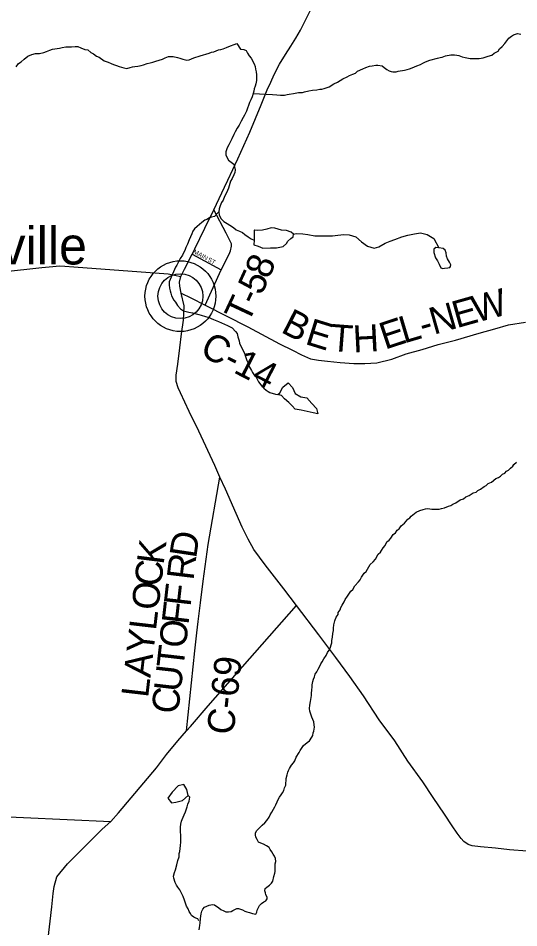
# Model space of a CAD drawing. Extents: x 1310247 to 1664935, y 235267 to 584339.
# Drawn here: x 1491906 to 1497464, y 346148 to 356246 of the extents above; entities that cross this region are included whole.
import ezdxf

# ---------------------------------------------------------------- set-up
doc = ezdxf.new("R2010")
doc.units = 0
for name, color, linetype in [('GM_X_County_Road', 7, 'Continuous'), ('GM_X_County_Road_Text', 7, 'Continuous'), ('GM_X_Minor_Lake', 7, 'Continuous'), ('GM_X_Minor_River', 7, 'Continuous'), ('GM_X_State_Route', 7, 'Continuous'), ('GM_X_Township_Road', 7, 'Continuous'), ('GM_X_Township_Road_Text', 7, 'Continuous'), ('GM_X_Township_Subdivision', 7, 'Continuous'), ('GM_X_Township_Subdivision_Text', 7, 'Continuous'), ('GM_X_Unincorporated', 7, 'Continuous'), ('GM_X_Unincorporated_Location', 7, 'Continuous'), ('GM_X_Unincorporated_Text', 7, 'Continuous')]:
    doc.layers.add(name, color=color, linetype=linetype)

msp = doc.modelspace()

# ---------------------------------------------------------------- linework, layer by layer
at = {"layer": 'GM_X_County_Road'}
for points in [[(1491734, 353430), (1492170, 353477), (1492252, 353485), (1492368, 353496), (1492426, 353492), (1492524, 353486), (1493570, 353407), (1493712, 353378)], [(1493716, 353192), (1493822, 353140)], [(1493822, 353140), (1493982, 353061), (1494456, 352818), (1494809, 352631), (1494952, 352559), (1495051, 352508), (1495150, 352466), (1495242, 352449), (1495341, 352439), (1495479, 352425), (1495633, 352411), (1495754, 352411), (1495887, 352419), (1496054, 352462), (1496214, 352518), (1496390, 352568), (1496570, 352622), (1496760, 352673), (1497025, 352750), (1497197, 352799), (1497351, 352841), (1497540, 352873)], [(1493776, 348333), (1493868, 349221), (1493889, 349421), (1493905, 349549), (1493930, 349754), (1493961, 349998), (1494016, 350403), (1494145, 351149)], [(1492058, 344014), (1492056, 344220), (1492071, 344510), (1492091, 344721), (1492130, 345110), (1492281, 346381), (1492294, 346529), (1492304, 346605), (1492334, 346713), (1492452, 346859), (1492839, 347242), (1492933, 347327), (1493021, 347424), (1493440, 347924), (1493552, 348071), (1493678, 348222), (1493776, 348333), (1493819, 348382), (1494015, 348612), (1494995, 349727)]]:
    msp.add_lwpolyline(points, dxfattribs=at)
at = {"layer": 'GM_X_Minor_Lake'}
for points in [[(1493794, 347618), (1493777, 347683), (1493746, 347739), (1493682, 347724), (1493614, 347655), (1493569, 347586)], [(1493569, 347586), (1493608, 347537), (1493655, 347544), (1493731, 347563), (1493794, 347618)], [(1493811, 347597), (1493794, 347618)]]:
    msp.add_lwpolyline(points, dxfattribs=at)
at = {"layer": 'GM_X_Minor_River'}
msp.add_line((1496575, 353695), (1496544, 353700), dxfattribs=at)
for points in [[(1494516, 355411), (1494731, 355397), (1494779, 355395), (1494820, 355390), (1494864, 355393), (1494892, 355397), (1494914, 355402), (1494961, 355410), (1495019, 355419), (1495063, 355422), (1495084, 355427), (1495134, 355441), (1495174, 355446), (1495221, 355451), (1495255, 355457), (1495279, 355458), (1495305, 355466), (1495358, 355485), (1495411, 355518), (1495451, 355536), (1495512, 355573), (1495559, 355596), (1495583, 355608), (1495620, 355623), (1495650, 355637), (1495675, 355658), (1495731, 355682), (1495766, 355697), (1495806, 355712), (1495836, 355718), (1495877, 355725), (1495899, 355725), (1495947, 355716), (1495969, 355700), (1495999, 355677), (1496026, 355660), (1496046, 355654), (1496066, 355650), (1496103, 355651), (1496125, 355657), (1496195, 355668), (1496224, 355677), (1496250, 355685), (1496280, 355694), (1496331, 355717), (1496371, 355731), (1496400, 355746), (1496428, 355760), (1496475, 355779), (1496560, 355802), (1496592, 355809), (1496612, 355813), (1496650, 355828), (1496709, 355840), (1496749, 355839), (1496775, 355836), (1496799, 355830), (1496837, 355817), (1496869, 355811), (1496923, 355800), (1496969, 355797), (1497024, 355798), (1497068, 355807), (1497125, 355824), (1497165, 355836), (1497190, 355857), (1497234, 355881), (1497251, 355905), (1497281, 355930), (1497308, 355964), (1497331, 355996), (1497355, 356023), (1497384, 356047), (1497404, 356061), (1497449, 356074), (1497487, 356069)], [(1491883, 355707), (1491911, 355741), (1491938, 355762), (1491972, 355790), (1492015, 355823), (1492059, 355843), (1492097, 355852), (1492143, 355855), (1492190, 355866), (1492220, 355876), (1492258, 355891), (1492288, 355903), (1492365, 355914), (1492395, 355919), (1492435, 355928), (1492463, 355926), (1492499, 355929), (1492539, 355931), (1492569, 355932), (1492601, 355916), (1492647, 355899), (1492678, 355894), (1492712, 355866), (1492744, 355849), (1492777, 355824), (1492805, 355812), (1492861, 355771), (1492904, 355756), (1492938, 355743), (1492964, 355731), (1492998, 355720), (1493026, 355708), (1493079, 355693), (1493111, 355688), (1493150, 355700), (1493176, 355705), (1493202, 355709), (1493234, 355714), (1493270, 355720), (1493296, 355727), (1493338, 355742), (1493373, 355750), (1493401, 355757), (1493433, 355767), (1493473, 355780), (1493507, 355792), (1493538, 355805), (1493576, 355821), (1493626, 355822), (1493674, 355811), (1493702, 355802), (1493734, 355792), (1493777, 355779), (1493804, 355785), (1493858, 355806), (1493926, 355829), (1494025, 355857), (1494051, 355867), (1494077, 355874), (1494130, 355893), (1494156, 355899), (1494182, 355907), (1494220, 355922), (1494265, 355939), (1494303, 355953), (1494333, 355964), (1494374, 355903), (1494410, 355899), (1494436, 355888), (1494451, 355856), (1494471, 355827), (1494492, 355801), (1494525, 355740), (1494537, 355708), (1494540, 355678), (1494548, 355650), (1494553, 355617), (1494552, 355555), (1494544, 355517), (1494537, 355491), (1494527, 355463), (1494522, 355437), (1494516, 355411)], [(1494516, 355411), (1494503, 355371), (1494489, 355338), (1494476, 355308), (1494464, 355276), (1494451, 355246), (1494440, 355212), (1494420, 355168), (1494405, 355142), (1494381, 355101), (1494360, 355059), (1494339, 355025), (1494315, 354983), (1494300, 354954), (1494277, 354906), (1494263, 354878), (1494246, 354840), (1494228, 354808), (1494211, 354763), (1494212, 354728), (1494222, 354702), (1494241, 354670), (1494269, 354647), (1494301, 354625), (1494308, 354594), (1494314, 354564), (1494311, 354534), (1494301, 354506), (1494280, 354466), (1494265, 354437), (1494248, 354385), (1494242, 354359), (1494230, 354333), (1494215, 354299), (1494198, 354265), (1494182, 354227), (1494165, 354200), (1494149, 354164), (1494136, 354130), (1494132, 354096), (1494139, 354060), (1494160, 354017), (1494190, 353987), (1494225, 353968), (1494257, 353947), (1494297, 353922), (1494328, 353898), (1494364, 353883), (1494398, 353865), (1494424, 353844), (1494459, 353817), (1494491, 353795), (1494525, 353782)], [(1494132, 354096), (1494084, 354044), (1494053, 354037), (1494031, 354029), (1494001, 354012), (1493978, 354004), (1493944, 353976), (1493895, 353933), (1493862, 353907), (1493846, 353882), (1493833, 353852), (1493806, 353784), (1493785, 353738), (1493766, 353702), (1493761, 353678), (1493732, 353616), (1493703, 353577), (1493693, 353555), (1493666, 353503), (1493651, 353483), (1493630, 353429), (1493612, 353391), (1493605, 353371), (1493593, 353344), (1493584, 353318), (1493582, 353287), (1493585, 353247), (1493592, 353219), (1493602, 353195), (1493609, 353162), (1493633, 353116), (1493652, 353095), (1493676, 353057), (1493709, 353020), (1493743, 352997), (1493801, 352984), (1493841, 352976), (1493913, 352956), (1493939, 352950), (1493985, 352935), (1494017, 352926), (1494075, 352901), (1494131, 352878), (1494165, 352863), (1494229, 352834), (1494282, 352809), (1494320, 352766), (1494337, 352744), (1494345, 352708), (1494360, 352665), (1494364, 352639), (1494397, 352568), (1494418, 352526), (1494426, 352501), (1494445, 352445), (1494456, 352424), (1494475, 352372), (1494497, 352333), (1494509, 352313), (1494528, 352281), (1494550, 352260), (1494573, 352210), (1494610, 352159), (1494632, 352138), (1494660, 352118), (1494680, 352101), (1494699, 352089), (1494763, 352072), (1494789, 352068)], [(1494525, 353782), (1494521, 353730), (1494569, 353715), (1494622, 353692), (1494709, 353696), (1494773, 353695), (1494849, 353710), (1494884, 353745), (1494898, 353769), (1494933, 353801), (1494959, 353818), (1494962, 353848), (1494936, 353871), (1494884, 353888), (1494828, 353893), (1494756, 353914)], [(1494756, 353914), (1494714, 353917), (1494668, 353904), (1494618, 353894), (1494558, 353889), (1494528, 353892), (1494526, 353892), (1494525, 353782)], [(1494962, 353848), (1494994, 353856), (1495066, 353852), (1495122, 353843), (1495200, 353830), (1495318, 353828), (1495394, 353831), (1495455, 353838), (1495523, 353846), (1495581, 353841), (1495655, 353818), (1495718, 353763), (1495785, 353715), (1495857, 353692), (1495911, 353709), (1495982, 353750), (1496035, 353771), (1496087, 353788), (1496164, 353817), (1496232, 353836), (1496307, 353853), (1496373, 353863), (1496447, 353846), (1496520, 353801), (1496575, 353695)], [(1496544, 353700), (1496520, 353682), (1496522, 353644), (1496541, 353584), (1496560, 353551), (1496579, 353515), (1496599, 353474), (1496621, 353466), (1496639, 353469), (1496675, 353473), (1496697, 353478), (1496707, 353488), (1496708, 353506), (1496694, 353539), (1496673, 353575), (1496663, 353603), (1496658, 353640)], [(1496658, 353640), (1496648, 353670), (1496623, 353688), (1496575, 353695)], [(1494789, 352068), (1494811, 352087), (1494844, 352151), (1494903, 352198), (1494951, 352147), (1494981, 352078), (1495043, 352043), (1495111, 352032), (1495166, 351970), (1495217, 351913), (1495232, 351855), (1495180, 351866), (1495116, 351879), (1495046, 351896), (1494982, 351905)], [(1494982, 351905), (1494949, 351942), (1494910, 351979), (1494864, 352022), (1494829, 352059), (1494789, 352068)], [(1495815, 350183), (1495847, 350209), (1495872, 350241), (1495901, 350296), (1495928, 350318), (1495940, 350338), (1495957, 350366), (1495979, 350393), (1496000, 350431), (1496024, 350451), (1496045, 350475), (1496070, 350516), (1496094, 350532), (1496113, 350562), (1496137, 350577), (1496158, 350611), (1496195, 350639), (1496232, 350684), (1496254, 350698), (1496270, 350718), (1496305, 350749), (1496326, 350761), (1496366, 350782), (1496404, 350792), (1496429, 350799), (1496455, 350801), (1496499, 350796), (1496545, 350795), (1496579, 350797), (1496606, 350804), (1496640, 350812), (1496685, 350829), (1496709, 350837), (1496731, 350852), (1496764, 350864), (1496814, 350899), (1496849, 350909), (1496875, 350932), (1496912, 350946), (1496959, 350975), (1496989, 350985), (1497009, 351004), (1497038, 351018), (1497078, 351047), (1497103, 351057), (1497125, 351079), (1497160, 351094), (1497209, 351135), (1497239, 351147), (1497259, 351161), (1497284, 351184), (1497308, 351196), (1497327, 351216), (1497351, 351227), (1497371, 351249), (1497396, 351273), (1497408, 351293), (1497437, 351316)], [(1494575, 347098), (1494561, 347127), (1494544, 347155), (1494540, 347179), (1494540, 347199), (1494551, 347225), (1494584, 347259), (1494616, 347286), (1494645, 347314), (1494668, 347338), (1494692, 347377), (1494705, 347401), (1494724, 347433), (1494740, 347465), (1494757, 347491), (1494765, 347515), (1494780, 347547), (1494792, 347574), (1494809, 347600), (1494824, 347624), (1494842, 347648), (1494855, 347674), (1494863, 347702), (1494876, 347730), (1494878, 347756), (1494883, 347780), (1494883, 347804), (1494892, 347848), (1494898, 347876), (1494909, 347896), (1494917, 347918), (1494942, 347953), (1494961, 347979), (1494977, 348003), (1494992, 348041), (1495027, 348094), (1495037, 348116), (1495052, 348140), (1495075, 348172), (1495115, 348207), (1495140, 348225), (1495165, 348263), (1495179, 348283), (1495182, 348311), (1495188, 348331), (1495195, 348377), (1495193, 348403), (1495188, 348435), (1495167, 348488), (1495144, 348554), (1495142, 348582), (1495145, 348619), (1495152, 348659), (1495159, 348703), (1495161, 348727), (1495164, 348753), (1495166, 348787), (1495169, 348825), (1495171, 348845), (1495178, 348881), (1495184, 348909), (1495195, 348935), (1495204, 348963), (1495222, 348989), (1495235, 349019), (1495255, 349052), (1495266, 349078), (1495280, 349102), (1495299, 349134), (1495324, 349172), (1495341, 349204), (1495359, 349229), (1495372, 349263), (1495382, 349289), (1495387, 349313), (1495389, 349337), (1495396, 349373), (1495401, 349417), (1495405, 349447), (1495408, 349473), (1495412, 349512), (1495423, 349556), (1495436, 349597), (1495457, 349627), (1495459, 349649), (1495480, 349677), (1495490, 349703), (1495503, 349731), (1495524, 349767), (1495538, 349793), (1495561, 349828), (1495600, 349884), (1495623, 349904), (1495643, 349945), (1495684, 349987), (1495701, 350011), (1495718, 350042), (1495749, 350086), (1495769, 350104), (1495785, 350128), (1495815, 350183)], [(1493910, 346226), (1493900, 346247), (1493878, 346257), (1493856, 346265), (1493830, 346284), (1493819, 346306), (1493805, 346331), (1493792, 346359), (1493774, 346389), (1493751, 346456), (1493738, 346494), (1493720, 346531), (1493699, 346571), (1493677, 346600), (1493664, 346622), (1493650, 346650), (1493635, 346701), (1493629, 346723), (1493640, 346763), (1493651, 346793), (1493666, 346849), (1493679, 346895), (1493692, 346937), (1493694, 346973), (1493699, 346997), (1493708, 347061), (1493713, 347099), (1493713, 347121), (1493713, 347151), (1493712, 347171), (1493709, 347222), (1493710, 347266), (1493712, 347300), (1493721, 347332), (1493727, 347352), (1493738, 347376), (1493748, 347404), (1493763, 347436), (1493774, 347468), (1493784, 347491), (1493791, 347519), (1493803, 347555), (1493811, 347597)], [(1493916, 346126), (1493920, 346150), (1493923, 346172), (1493925, 346202), (1493932, 346250), (1493935, 346278), (1493939, 346304), (1493946, 346332), (1493958, 346356), (1493975, 346376), (1494027, 346401), (1494062, 346408), (1494084, 346402), (1494135, 346369), (1494155, 346351), (1494189, 346336), (1494213, 346326), (1494241, 346327), (1494269, 346331), (1494290, 346340), (1494310, 346352), (1494332, 346364), (1494352, 346361), (1494376, 346355), (1494396, 346346), (1494422, 346334), (1494446, 346324), (1494476, 346317), (1494508, 346308), (1494544, 346300), (1494557, 346320), (1494559, 346344), (1494572, 346368), (1494584, 346395), (1494607, 346419), (1494633, 346437), (1494655, 346446), (1494670, 346468), (1494670, 346490), (1494657, 346515), (1494651, 346535), (1494643, 346557), (1494648, 346585), (1494668, 346601), (1494697, 346622), (1494719, 346644), (1494732, 346666), (1494743, 346718), (1494757, 346754), (1494760, 346774), (1494760, 346794), (1494759, 346822), (1494761, 346860), (1494766, 346884), (1494762, 346916), (1494751, 346945), (1494737, 346965), (1494724, 346991), (1494704, 347018), (1494694, 347038), (1494664, 347057), (1494631, 347077), (1494599, 347086), (1494575, 347098)]]:
    msp.add_lwpolyline(points, dxfattribs=at)
at = {"layer": 'GM_X_State_Route'}
for points in [[(1494234, 354448), (1494343, 354683), (1494477, 354982), (1494603, 355283), (1494670, 355449), (1494710, 355537), (1494747, 355620), (1494806, 355734), (1494875, 355843), (1494934, 355934), (1494989, 356023), (1495041, 356113), (1495115, 356259), (1495208, 356446), (1495271, 356586), (1495350, 356750), (1495409, 356872), (1495415, 356887)], [(1497556, 347000), (1497362, 347014), (1497204, 347031), (1497040, 347047), (1496947, 347059), (1496900, 347074), (1496853, 347105), (1496823, 347139), (1496781, 347197), (1496724, 347280), (1496639, 347408), (1496514, 347595), (1496397, 347767), (1496233, 347998), (1496088, 348222), (1495913, 348458), (1495740, 348725), (1495589, 348938), (1495431, 349149), (1495245, 349401), (1494995, 349727), (1494855, 349910), (1494648, 350176), (1494523, 350348), (1494460, 350462), (1494393, 350595), (1494327, 350747), (1494208, 351016), (1494145, 351149), (1494090, 351281), (1493910, 351660), (1493804, 351879), (1493707, 352086), (1493683, 352141), (1493661, 352214), (1493660, 352282), (1493680, 352404), (1493701, 352586), (1493721, 352741), (1493740, 352894), (1493747, 352966), (1493750, 353053), (1493716, 353192), (1493699, 353272), (1493698, 353317), (1493712, 353378), (1493754, 353460), (1493837, 353626), (1493867, 353687), (1493980, 353916), (1494077, 354118), (1494198, 354371), (1494234, 354448)]]:
    msp.add_lwpolyline(points, dxfattribs=at)
at = {"layer": 'GM_X_Township_Road'}
for points in [[(1493982, 353061), (1494158, 353452), (1494250, 353625), (1494262, 353665), (1494273, 353715), (1494274, 353742), (1494214, 353858), (1494077, 354118)], [(1490991, 347416), (1492933, 347327)]]:
    msp.add_lwpolyline(points, dxfattribs=at)
at = {"layer": 'GM_X_Township_Subdivision'}
msp.add_lwpolyline([(1493837, 353626), (1494158, 353452)], dxfattribs=at)
at = {"layer": 'GM_X_Unincorporated'}
for radius in [393, 249]:
    msp.add_circle((1493707, 353160), radius, dxfattribs=at)
at = {"layer": 'GM_X_Unincorporated_Location'}
msp.add_line((1493707, 353160), (1493707, 353160), dxfattribs=at)

# ---------------------------------------------------------------- texts
at = {"layer": 'GM_X_County_Road_Text'}
for s, rotation, p in [('W', 14.8207, (1496988, 352864)), ('E', 15.7807, (1496774, 352803)), ('B', 332.8626, (1494811, 352765)), ('N', 15.884, (1496520, 352731)), ('E', 342.7756, (1495080, 352632)), ('E', 18.235, (1495978, 352564)), ('L', 16.4732, (1496188, 352633)), ('T', 355.5966, (1495365, 352553)), ('H', 2.9214, (1495629, 352535)), ('-', 16.1737, (1496403, 352697)), ('C-14', 332.6703, (1493909, 352512)), ('D', 81.433, (1493881, 350242)), ('K', 82.8049, (1493520, 350172)), ('R', 83.1103, (1493852, 349999)), ('C', 83.3501, (1493492, 349928)), ('O', 83.348, (1493461, 349665)), ('F', 83.467, (1493819, 349707)), ('F', 83.4717, (1493796, 349506)), ('L', 83.3502, (1493435, 349442)), ('O', 83.4704, (1493766, 349244)), ('Y', 83.348, (1493405, 349180)), ('T', 83.4717, (1493740, 349021)), ('A', 83.3478, (1493374, 348918)), ('C-69', 83.8122, (1494297, 348282)), ('U', 83.4714, (1493710, 348758)), ('L', 83.351, (1493348, 348695)), ('C', 83.4719, (1493682, 348514))]:
    msp.add_text(s, height=300, rotation=rotation, dxfattribs=at).set_placement(p)
at = {"layer": 'GM_X_Township_Road_Text'}
for s, rotation, p in [('8', 67.614, (1494689, 353339)), ('5', 65.1097, (1494605, 353158)), ('T', 64.8869, (1494457, 352843)), ('-', 64.9309, (1494553, 353046))]:
    msp.add_text(s, height=300, rotation=rotation, dxfattribs=at).set_placement(p)
at = {"layer": 'GM_X_Township_Subdivision_Text'}
for s, rotation, p in [('MAIN', 330.641, (1493845, 353639)), ('ST', 330.2509, (1494004, 353551))]:
    msp.add_text(s, height=50, rotation=rotation, dxfattribs=at).set_placement(p)
at = {"layer": 'GM_X_Unincorporated_Text'}
msp.add_text('Nicholsville', height=417, rotation=0, dxfattribs=at).set_placement((1489881, 353512))

doc.saveas('drawing.dxf')
